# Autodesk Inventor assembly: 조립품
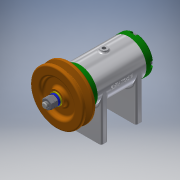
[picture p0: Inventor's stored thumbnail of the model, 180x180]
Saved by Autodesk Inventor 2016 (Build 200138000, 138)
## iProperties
Created: 2020-07
Part Number: 조립품
Material: 일반
Document SubType Name: Assembly
Designer: pc-04
Author: pc-04
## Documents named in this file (15)
- C:\Users\pc-04\Desktop\700706V1016\조립품.iam
- C:\Users\pc-04\Desktop\700706V1016\본체.ipt
- C:\Users\pc-04\Desktop\700706V1016\뒤커버.ipt
- C:\Users\pc-04\Desktop\700706V1016\베어링 6002.ipt
- C:\Users\pc-04\Desktop\700706V1016\축.ipt
- C:\Users\pc-04\Desktop\700706V1016\앞커버.ipt
- C:\Users\pc-04\Desktop\700706V1016\키 3x3x12.ipt
- C:\Users\pc-04\Desktop\700706V1016\V벨트풀리.ipt
- C:\Users\pc-04\Desktop\700706V1016\와셔 8x17.ipt
- C:\Users\pc-04\Desktop\700706V1016\스프링와셔 8.ipt
- C:\Users\pc-04\Desktop\700706V1016\너트 M8.ipt
- C:\Users\pc-04\Desktop\700706V1016\오일 실 15 25 7.ipt
- C:\Users\pc-04\Desktop\700706V1016\볼트 M4x12.ipt
- C:\Users\pc-04\Desktop\700706V1016\와셔 6x11.5.ipt
- C:\Users\pc-04\Desktop\700706V1016\볼트 M6x8.ipt
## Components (1 placed, 1 different names)
1. V벨트풀리:1
